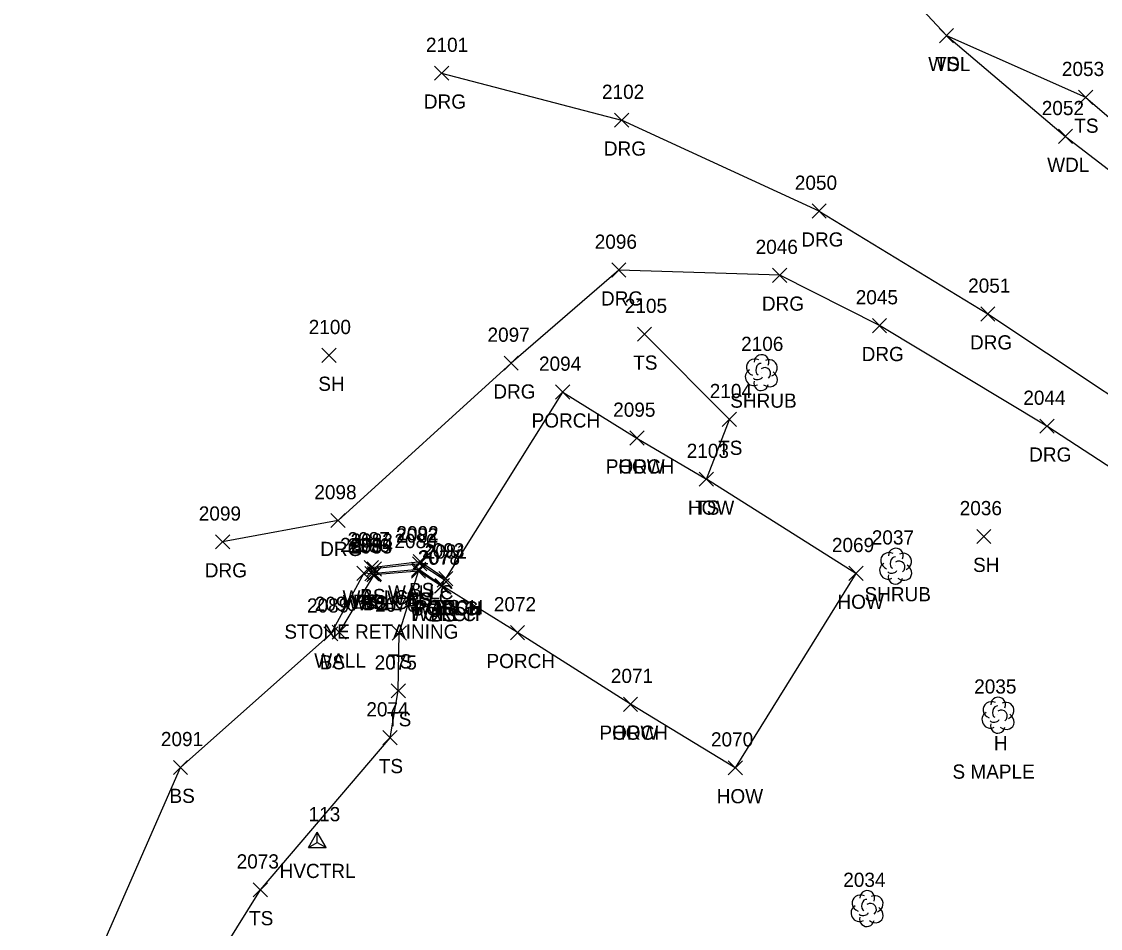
# Model space of a CAD drawing. Extents: x 1885914 to 1887218, y 756253 to 760620.
# Drawn here: x 1886318.4 to 1886470.3, y 760033 to 760160.7 of the extents above; entities that cross this region are included whole.
import ezdxf

# ---------------------------------------------------------------- set-up
doc = ezdxf.new("R2010")
doc.units = 0
for name, color, linetype in [('C_A', 7, 'Continuous'), ('C_I', 7, 'Continuous'), ('CPSM', 7, 'Continuous'), ('L_A', 7, 'Continuous'), ('L_C', 7, 'Continuous'), ('L_I', 7, 'Continuous'), ('L_TIC', 7, 'Continuous'), ('LAWA', 7, 'Continuous'), ('LBC', 7, 'Continuous'), ('LBF', 7, 'Continuous'), ('LELB', 7, 'Continuous'), ('LSH', 7, 'Continuous'), ('LTD', 7, 'Continuous'), ('LW', 7, 'Continuous'), ('R_A', 7, 'Continuous'), ('R_I', 7, 'Continuous'), ('R_TIC', 7, 'Continuous'), ('RDG', 7, 'Continuous')]:
    doc.layers.add(name, color=color, linetype=linetype)

msp = doc.modelspace()

# ---------------------------------------------------------------- linework, layer by layer
at = {"layer": 'CPSM'}
for p, q in [((1886358.8, 760044.34), (1886360.05, 760046.51)), ((1886361.3, 760044.34), (1886360.05, 760046.51)), ((1886360.05, 760045.06), (1886360.05, 760046.51)), ((1886358.8, 760044.34), (1886360.05, 760045.06)), ((1886360.05, 760045.06), (1886360.05, 760045.06)), ((1886360.05, 760045.06), (1886361.3, 760044.34)), ((1886358.8, 760044.34), (1886361.3, 760044.34))]:
    msp.add_line(p, q, dxfattribs=at)
at = {"layer": 'L_TIC'}
for points in [[(1886447.67, 760157.75), (1886449.67, 760159.75)], [(1886449.67, 760157.75), (1886447.67, 760159.75)], [(1886447.67, 760157.75), (1886449.67, 760159.75)], [(1886449.67, 760157.75), (1886447.67, 760159.75)], [(1886467.25, 760149.06), (1886469.25, 760151.06)], [(1886469.25, 760149.06), (1886467.25, 760151.06)], [(1886464.42, 760143.55), (1886466.42, 760145.55)], [(1886466.42, 760143.55), (1886464.42, 760145.55)], [(1886405.13, 760115.68), (1886407.13, 760117.68)], [(1886407.13, 760115.68), (1886405.13, 760117.68)], [(1886360.7, 760112.7), (1886362.7, 760114.7)], [(1886362.7, 760112.7), (1886360.7, 760114.7)], [(1886393.61, 760107.53), (1886395.61, 760109.53)], [(1886395.61, 760107.53), (1886393.61, 760109.53)], [(1886417.09, 760103.68), (1886419.09, 760105.68)], [(1886419.09, 760103.68), (1886417.09, 760105.68)], [(1886404.06, 760101.05), (1886406.06, 760103.05)], [(1886406.06, 760101.05), (1886404.06, 760103.05)], [(1886404.06, 760101.05), (1886406.06, 760103.05)], [(1886406.06, 760101.05), (1886404.06, 760103.05)], [(1886413.85, 760095.25), (1886415.85, 760097.25)], [(1886415.85, 760095.25), (1886413.85, 760097.25)], [(1886413.85, 760095.25), (1886415.85, 760097.25)], [(1886415.85, 760095.25), (1886413.85, 760097.25)], [(1886413.85, 760095.25), (1886415.85, 760097.25)], [(1886415.85, 760095.25), (1886413.85, 760097.25)], [(1886452.91, 760087.18), (1886454.91, 760089.18)], [(1886454.91, 760087.18), (1886452.91, 760089.18)], [(1886373.53, 760083.64), (1886375.53, 760085.64)], [(1886375.53, 760083.64), (1886373.53, 760085.64)], [(1886365.6, 760081.99), (1886367.6, 760083.99)], [(1886367.6, 760081.99), (1886365.6, 760083.99)], [(1886366.65, 760082.79), (1886368.65, 760084.79)], [(1886368.65, 760082.79), (1886366.65, 760084.79)], [(1886366.73, 760081.93), (1886368.73, 760083.93)], [(1886368.73, 760081.93), (1886366.73, 760083.93)], [(1886366.73, 760081.93), (1886368.73, 760083.93)], [(1886368.73, 760081.93), (1886366.73, 760083.93)], [(1886367.07, 760082.61), (1886369.07, 760084.61)], [(1886369.07, 760082.61), (1886367.07, 760084.61)], [(1886367.1, 760081.95), (1886369.1, 760083.95)], [(1886369.1, 760081.95), (1886367.1, 760083.95)], [(1886367.1, 760081.95), (1886369.1, 760083.95)], [(1886369.1, 760081.95), (1886367.1, 760083.95)], [(1886373.31, 760082.29), (1886375.31, 760084.29)], [(1886375.31, 760082.29), (1886373.31, 760084.29)], [(1886373.31, 760082.29), (1886375.31, 760084.29)], [(1886375.31, 760082.29), (1886373.31, 760084.29)], [(1886373.33, 760082.54), (1886375.33, 760084.54)], [(1886375.33, 760082.54), (1886373.33, 760084.54)], [(1886373.47, 760083.32), (1886375.47, 760085.32)], [(1886375.47, 760083.32), (1886373.47, 760085.32)], [(1886434.91, 760081.98), (1886436.91, 760083.98)], [(1886436.91, 760081.98), (1886434.91, 760083.98)], [(1886434.91, 760081.98), (1886436.91, 760083.98)], [(1886436.91, 760081.98), (1886434.91, 760083.98)], [(1886367.01, 760081.78), (1886369.01, 760083.78)], [(1886369.01, 760081.78), (1886367.01, 760083.78)], [(1886367.01, 760081.78), (1886369.01, 760083.78)], [(1886369.01, 760081.78), (1886367.01, 760083.78)], [(1886376.94, 760081.06), (1886378.94, 760083.06)], [(1886378.94, 760081.06), (1886376.94, 760083.06)], [(1886376.94, 760081.06), (1886378.94, 760083.06)], [(1886378.94, 760081.06), (1886376.94, 760083.06)], [(1886377.15, 760081.23), (1886379.15, 760083.23)], [(1886379.15, 760081.23), (1886377.15, 760083.23)], [(1886377.15, 760081.23), (1886379.15, 760083.23)], [(1886379.15, 760081.23), (1886377.15, 760083.23)], [(1886376.54, 760080.19), (1886378.54, 760082.19)], [(1886378.54, 760080.19), (1886376.54, 760082.19)], [(1886376.65, 760080.25), (1886378.65, 760082.25)], [(1886378.65, 760080.25), (1886376.65, 760082.25)], [(1886376.65, 760080.25), (1886378.65, 760082.25)], [(1886378.65, 760080.25), (1886376.65, 760082.25)], [(1886360.95, 760073.46), (1886362.95, 760075.46)], [(1886362.95, 760073.46), (1886360.95, 760075.46)], [(1886362.13, 760073.7), (1886364.13, 760075.7)], [(1886364.13, 760073.7), (1886362.13, 760075.7)], [(1886370.59, 760073.58), (1886372.59, 760075.58)], [(1886372.59, 760073.58), (1886370.59, 760075.58)], [(1886387.25, 760073.64), (1886389.25, 760075.64)], [(1886389.25, 760073.64), (1886387.25, 760075.64)], [(1886387.25, 760073.64), (1886389.25, 760075.64)], [(1886389.25, 760073.64), (1886387.25, 760075.64)], [(1886370.46, 760065.43), (1886372.46, 760067.43)], [(1886372.46, 760065.43), (1886370.46, 760067.43)], [(1886403.16, 760063.54), (1886405.16, 760065.54)], [(1886405.16, 760063.54), (1886403.16, 760065.54)], [(1886403.16, 760063.54), (1886405.16, 760065.54)], [(1886405.16, 760063.54), (1886403.16, 760065.54)], [(1886369.3, 760058.83), (1886371.3, 760060.83)], [(1886371.3, 760058.83), (1886369.3, 760060.83)], [(1886339.79, 760054.64), (1886341.79, 760056.64)], [(1886341.79, 760054.64), (1886339.79, 760056.64)], [(1886339.79, 760054.64), (1886341.79, 760056.64)], [(1886341.79, 760054.64), (1886339.79, 760056.64)], [(1886417.91, 760054.59), (1886419.91, 760056.59)], [(1886419.91, 760054.59), (1886417.91, 760056.59)], [(1886351.03, 760037.4), (1886353.03, 760039.4)], [(1886353.03, 760037.4), (1886351.03, 760039.4)]]:
    msp.add_lwpolyline(points, dxfattribs=at)
at = {"layer": 'LAWA'}
msp.add_lwpolyline([(1886410.21, 760202.66), (1886433.18, 760175.41), (1886448.67, 760158.75), (1886465.42, 760144.55), (1886489.64, 760125.96), (1886497.6, 760121.62), (1886524.44, 760097.09), (1886536.37, 760086.88), (1886546.94, 760096.36), (1886535.34, 760123.1)], dxfattribs=at)
at = {"layer": 'LBC'}
for points in [[(1886405.06, 760102.05), (1886414.85, 760096.25)], [(1886435.91, 760082.98), (1886414.85, 760096.25)], [(1886435.91, 760082.98), (1886418.91, 760055.59), (1886404.16, 760064.54)]]:
    msp.add_lwpolyline(points, dxfattribs=at)
at = {"layer": 'LBF'}
for points in [[(1886388.25, 760074.64), (1886377.65, 760081.25), (1886377.94, 760082.06), (1886378.15, 760082.23), (1886394.61, 760108.53), (1886405.06, 760102.05)], [(1886404.16, 760064.54), (1886388.25, 760074.64)]]:
    msp.add_lwpolyline(points, dxfattribs=at)
at = {"layer": 'LELB'}
for points in [[(1886448.67, 760158.75), (1886468.25, 760150.06), (1886490.6, 760130.85), (1886497.6, 760121.62)], [(1886414.85, 760096.25), (1886418.09, 760104.68), (1886406.13, 760116.68)], [(1886377.54, 760081.19), (1886374.31, 760083.29), (1886368.01, 760082.78), (1886367.73, 760082.93), (1886367.65, 760083.79), (1886374.53, 760084.64), (1886378.15, 760082.23)], [(1886330.28, 760003.4), (1886352.03, 760038.4), (1886370.3, 760059.83), (1886371.46, 760066.43), (1886371.59, 760074.58), (1886374.31, 760083.29)], [(1886367.73, 760082.93), (1886366.6, 760082.99), (1886361.95, 760074.46), (1886340.79, 760055.64)], [(1886318.4, 760004.48), (1886340.79, 760055.64)]]:
    msp.add_lwpolyline(points, dxfattribs=at)
at = {"layer": 'LSH'}
for p, q in [((1886422.57, 760111.32), (1886422.57, 760111.32)), ((1886422.57, 760111.32), (1886422.57, 760111.32)), ((1886441.48, 760084.05), (1886441.48, 760084.05)), ((1886441.48, 760084.05), (1886441.48, 760084.05))]:
    msp.add_line(p, q, dxfattribs=at)
for centre in [(1886422.61, 760112.75), (1886441.53, 760085.48)]:
    msp.add_arc(centre, 1.05, 335.5272, 180.9563, dxfattribs=at)
for centre, major_axis, ratio, start_param, end_param in [((1886421.78, 760111.98), (1.21, -0.51), 0.895232, 1.570796, 4.712389), ((1886423.61, 760111.9), (-1.14, -0.48), 0.949671, 1.570796, 4.712389), ((1886421.48, 760110.61), (0.58, -1.04), 0.959034, 3.141593, 6.283185), ((1886422.36, 760111.77), (-0.208, -0.792), 0.645439, 3.141593, 6.283185), ((1886423.07, 760111.15), (-0.5, 0.667), 0.989748, 3.141593, 6.283185), ((1886423.57, 760110.48), (-1.09, 0.79), 0.841452, 1.570796, 4.712389), ((1886422.57, 760109.82), (0.26, 1.06), 0.942809, 1.570796, 4.712389), ((1886422.11, 760110.57), (-0.625, -0.083), 0.423636, 0, 3.141593), ((1886440.69, 760084.71), (1.21, -0.51), 0.895232, 1.570796, 4.712389), ((1886442.52, 760084.63), (-1.14, -0.48), 0.949671, 1.570796, 4.712389), ((1886440.4, 760083.34), (0.58, -1.04), 0.959034, 3.141593, 6.283185), ((1886441.27, 760084.5), (-0.208, -0.792), 0.645439, 3.141593, 6.283185), ((1886441.98, 760083.88), (-0.5, 0.667), 0.989748, 3.141593, 6.283185), ((1886442.48, 760083.21), (-1.09, 0.79), 0.841452, 1.570796, 4.712389), ((1886441.48, 760082.55), (0.26, 1.06), 0.942809, 1.570796, 4.712389), ((1886441.02, 760083.3), (-0.625, -0.083), 0.423636, 0, 3.141593)]:
    msp.add_ellipse(centre, major_axis=major_axis, ratio=ratio, start_param=start_param, end_param=end_param, dxfattribs=at)
at = {"layer": 'LTD'}
for p, q in [((1886455.9, 760063.05), (1886455.9, 760063.05)), ((1886455.9, 760063.05), (1886455.9, 760063.05)), ((1886437.46, 760035.81), (1886437.46, 760035.81)), ((1886437.46, 760035.81), (1886437.46, 760035.81))]:
    msp.add_line(p, q, dxfattribs=at)
for centre in [(1886455.94, 760064.48), (1886437.5, 760037.24)]:
    msp.add_arc(centre, 1.05, 335.5272, 180.9563, dxfattribs=at)
for centre, major_axis, ratio, start_param, end_param in [((1886455.11, 760063.71), (1.21, -0.51), 0.895232, 1.570796, 4.712389), ((1886455.69, 760063.51), (-0.208, -0.792), 0.645439, 3.141593, 6.283185), ((1886456.94, 760063.63), (-1.14, -0.48), 0.949671, 1.570796, 4.712389), ((1886454.81, 760062.34), (0.58, -1.04), 0.959034, 3.141593, 6.283185), ((1886456.4, 760062.88), (-0.5, 0.667), 0.989748, 3.141593, 6.283185), ((1886456.9, 760062.21), (-1.09, 0.79), 0.841452, 1.570796, 4.712389), ((1886455.9, 760061.55), (0.26, 1.06), 0.942809, 1.570796, 4.712389), ((1886455.44, 760062.3), (-0.625, -0.083), 0.423636, 0, 3.141593), ((1886436.67, 760036.47), (1.21, -0.51), 0.895232, 1.570796, 4.712389), ((1886437.25, 760036.26), (-0.208, -0.792), 0.645439, 3.141593, 6.283185), ((1886438.5, 760036.39), (-1.14, -0.48), 0.949671, 1.570796, 4.712389), ((1886436.37, 760035.1), (0.58, -1.04), 0.959034, 3.141593, 6.283185), ((1886437.96, 760035.64), (-0.5, 0.667), 0.989748, 3.141593, 6.283185), ((1886438.46, 760034.97), (-1.09, 0.79), 0.841452, 1.570796, 4.712389), ((1886437.46, 760034.31), (0.26, 1.06), 0.942809, 1.570796, 4.712389), ((1886437, 760035.05), (-0.625, -0.083), 0.423636, 0, 3.141593)]:
    msp.add_ellipse(centre, major_axis=major_axis, ratio=ratio, start_param=start_param, end_param=end_param, dxfattribs=at)
at = {"layer": 'LW'}
for points in [[(1886377.94, 760082.06), (1886374.47, 760084.32), (1886368.07, 760083.61), (1886368.1, 760082.95)], [(1886368.01, 760082.78), (1886363.13, 760074.7)], [(1886377.65, 760081.25), (1886374.33, 760083.54), (1886368.1, 760082.95)]]:
    msp.add_lwpolyline(points, dxfattribs=at)
at = {"layer": 'R_TIC'}
for points in [[(1886376.56, 760152.46), (1886378.56, 760154.46)], [(1886378.56, 760152.46), (1886376.56, 760154.46)], [(1886401.91, 760145.84), (1886403.91, 760147.84)], [(1886403.91, 760145.84), (1886401.91, 760147.84)], [(1886401.91, 760145.84), (1886403.91, 760147.84)], [(1886403.91, 760145.84), (1886401.91, 760147.84)], [(1886429.72, 760133.03), (1886431.72, 760135.03)], [(1886431.72, 760133.03), (1886429.72, 760135.03)], [(1886429.72, 760133.03), (1886431.72, 760135.03)], [(1886431.72, 760133.03), (1886429.72, 760135.03)], [(1886401.51, 760124.72), (1886403.51, 760126.72)], [(1886403.51, 760124.72), (1886401.51, 760126.72)], [(1886424.17, 760123.99), (1886426.17, 760125.99)], [(1886426.17, 760123.99), (1886424.17, 760125.99)], [(1886453.48, 760118.53), (1886455.48, 760120.53)], [(1886455.48, 760118.53), (1886453.48, 760120.53)], [(1886438.22, 760116.89), (1886440.22, 760118.89)], [(1886440.22, 760116.89), (1886438.22, 760118.89)], [(1886386.36, 760111.61), (1886388.36, 760113.61)], [(1886388.36, 760111.61), (1886386.36, 760113.61)], [(1886461.81, 760102.73), (1886463.81, 760104.73)], [(1886463.81, 760102.73), (1886461.81, 760104.73)], [(1886361.97, 760089.43), (1886363.97, 760091.43)], [(1886363.97, 760089.43), (1886361.97, 760091.43)], [(1886345.71, 760086.42), (1886347.71, 760088.42)], [(1886347.71, 760086.42), (1886345.71, 760088.42)]]:
    msp.add_lwpolyline(points, dxfattribs=at)
at = {"layer": 'RDG'}
for points in [[(1886377.56, 760153.46), (1886402.91, 760146.84)], [(1886430.72, 760134.03), (1886402.91, 760146.84)], [(1886430.72, 760134.03), (1886454.48, 760119.53), (1886487.38, 760097.68)], [(1886535.57, 760041.14), (1886534.93, 760050.62), (1886528.91, 760059.18), (1886516.23, 760069.22), (1886491.88, 760084.76), (1886462.81, 760103.73), (1886439.22, 760117.89), (1886425.17, 760124.99), (1886402.51, 760125.72), (1886387.36, 760112.61), (1886362.97, 760090.43), (1886346.71, 760087.42)]]:
    msp.add_lwpolyline(points, dxfattribs=at)

# ---------------------------------------------------------------- texts
at = {"layer": 'C_A'}
msp.add_text('HVCTRL', height=2, dxfattribs=at).set_placement((1886354.74, 760040.06))
at = {"layer": 'C_I'}
msp.add_text('113', height=2, dxfattribs=at).set_placement((1886358.82, 760048.06))
at = {"layer": 'L_A'}
for s, p in [('WDL', (1886446.09, 760153.75)), ('TS', (1886447.08, 760153.75)), ('TS', (1886466.66, 760145.06)), ('WDL', (1886462.84, 760139.55)), ('TS', (1886404.54, 760111.68)), ('SH', (1886360.19, 760108.7)), ('SHRUB', (1886418.2, 760106.32)), ('PORCH', (1886390.23, 760103.53)), ('TS', (1886416.5, 760099.68)), ('PORCH', (1886400.68, 760097.05)), ('HOW', (1886402.44, 760097.05)), ('HOW', (1886412.24, 760091.25)), ('HOW', (1886412.24, 760091.25)), ('TS', (1886413.26, 760091.25)), ('SH', (1886452.4, 760083.18)), ('BS', (1886366.09, 760078.79)), ('WALLC', (1886370.01, 760079.32)), ('BS', (1886372.97, 760079.64)), ('SHRUB', (1886437.11, 760079.05)), ('WALLC', (1886363.6, 760078.61)), ('WALLC', (1886363.63, 760077.95)), ('WALLC', (1886363.63, 760077.95)), ('WALL', (1886364.5, 760077.78)), ('BS', (1886365.04, 760077.99)), ('BS', (1886366.17, 760077.93)), ('BS', (1886366.17, 760077.93)), ('BS', (1886366.45, 760077.78)), ('WALLC', (1886369.87, 760078.54)), ('TS', (1886372.72, 760078.29)), ('BS', (1886372.76, 760078.29)), ('HOW', (1886433.3, 760077.98)), ('HOW', (1886433.3, 760077.98)), ('WALLC', (1886373.19, 760076.25)), ('WALLC', (1886373.47, 760077.06)), ('PORCH', (1886373.27, 760076.25)), ('PORCH', (1886373.56, 760077.06)), ('PORCH', (1886373.78, 760077.23)), ('BS', (1886375.98, 760076.19)), ('BS', (1886376.6, 760077.23)), ('WALL', (1886359.62, 760069.7)), ('BS', (1886360.39, 760069.46)), ('TS', (1886370, 760069.58)), ('PORCH', (1886383.87, 760069.64)), ('PORCH', (1886383.87, 760069.64)), ('TS', (1886369.87, 760061.43)), ('PORCH', (1886399.78, 760059.54)), ('HOW', (1886401.55, 760059.54)), ('H', (1886455.33, 760058.05)), ('TS', (1886368.71, 760054.83)), ('BS', (1886339.23, 760050.64)), ('BS', (1886339.23, 760050.64)), ('HOW', (1886416.3, 760050.59)), ('TS', (1886350.44, 760033.4))]:
    msp.add_text(s, height=2, dxfattribs=at).set_placement(p)
at = {"layer": 'L_C'}
for s, p in [('STONE RETAINING', (1886355.41, 760073.78)), ('S MAPLE', (1886449.5, 760054.05))]:
    msp.add_text(s, height=2, dxfattribs=at).set_placement(p)
at = {"layer": 'L_I'}
for s, p in [('2053', (1886464.91, 760153.06)), ('2052', (1886462.08, 760147.55)), ('2105', (1886403.36, 760119.68)), ('2100', (1886358.84, 760116.7)), ('2106', (1886419.74, 760114.32)), ('2094', (1886391.27, 760111.53)), ('2104', (1886415.32, 760107.68)), ('2095', (1886401.72, 760105.05)), ('2095', (1886401.72, 760105.05)), ('2103', (1886412.08, 760099.25)), ('2103', (1886412.08, 760099.25)), ('2103', (1886412.08, 760099.25)), ('2036', (1886450.52, 760091.18)), ('2087', (1886364.31, 760086.79)), ('2083', (1886364.73, 760086.61)), ('2080', (1886370.91, 760086.54)), ('2082', (1886371.13, 760087.32)), ('2092', (1886371.19, 760087.64)), ('2037', (1886438.14, 760087.05)), ('2088', (1886363.26, 760085.99)), ('2086', (1886364.33, 760085.93)), ('2086', (1886364.33, 760085.93)), ('2085', (1886364.67, 760085.78)), ('2085', (1886364.67, 760085.78)), ('2084', (1886364.76, 760085.95)), ('2084', (1886364.76, 760085.95)), ('2079', (1886370.97, 760086.29)), ('2079', (1886370.97, 760086.29)), ('2093', (1886374.82, 760085.23)), ('2093', (1886374.82, 760085.23)), ('2081', (1886375.17, 760085.06)), ('2081', (1886375.17, 760085.06)), ('2069', (1886432.52, 760085.98)), ('2069', (1886432.52, 760085.98)), ('2078', (1886374.2, 760084.19)), ('2077', (1886374.31, 760084.25)), ('2077', (1886374.31, 760084.25)), ('2089', (1886358.6, 760077.46)), ('2090', (1886359.7, 760077.7)), ('2076', (1886368.2, 760077.58)), ('2072', (1886384.91, 760077.64)), ('2072', (1886384.91, 760077.64)), ('2075', (1886368.12, 760069.43)), ('2071', (1886401.39, 760067.54)), ('2071', (1886401.39, 760067.54)), ('2035', (1886452.56, 760066.05)), ('2074', (1886366.96, 760062.83)), ('2091', (1886338.02, 760058.64)), ('2091', (1886338.02, 760058.64)), ('2070', (1886415.49, 760058.59)), ('2073', (1886348.69, 760041.4)), ('2034', (1886434.12, 760038.81))]:
    msp.add_text(s, height=2, dxfattribs=at).set_placement(p)
at = {"layer": 'R_A'}
for p in [(1886375.05, 760148.46), (1886400.4, 760141.84), (1886400.4, 760141.84), (1886428.21, 760129.03), (1886428.21, 760129.03), (1886400, 760120.72), (1886422.66, 760119.99), (1886451.97, 760114.53), (1886436.71, 760112.89), (1886384.84, 760107.61), (1886460.3, 760098.73), (1886360.46, 760085.43), (1886344.2, 760082.42)]:
    msp.add_text('DRG', height=2, dxfattribs=at).set_placement(p)
at = {"layer": 'R_I'}
for s, p in [('2101', (1886375.35, 760156.46)), ('2102', (1886400.14, 760149.84)), ('2102', (1886400.14, 760149.84)), ('2050', (1886427.3, 760137.03)), ('2050', (1886427.3, 760137.03)), ('2096', (1886399.12, 760128.72)), ('2046', (1886421.78, 760127.99)), ('2051', (1886451.71, 760122.53)), ('2045', (1886435.88, 760120.89)), ('2097', (1886384.02, 760115.61)), ('2044', (1886459.48, 760106.73)), ('2098', (1886359.63, 760093.43)), ('2099', (1886343.36, 760090.42))]:
    msp.add_text(s, height=2, dxfattribs=at).set_placement(p)

doc.saveas('drawing.dxf')
